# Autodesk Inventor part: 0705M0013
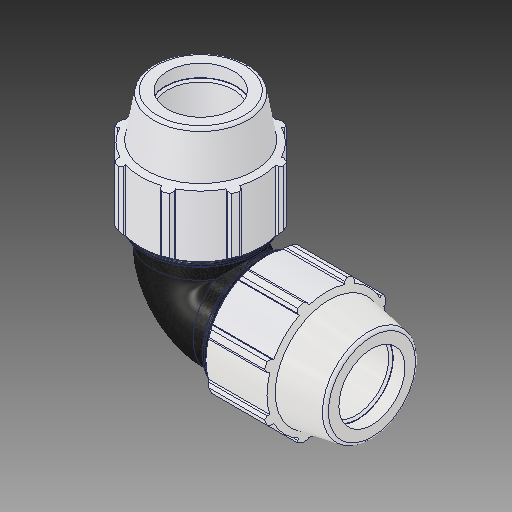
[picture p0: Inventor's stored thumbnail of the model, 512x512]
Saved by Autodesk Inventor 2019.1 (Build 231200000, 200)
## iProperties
Created: 2017-02
Part Number: 0705M0013
Material: PVC-Piping
Description: PLASSON 90° ELBOW 1 1/4'' - 1 1/4''
Document SubType Name: Modeling
Designer: KIM
Mass: 92.6774 g
Surface Area: 199.44 cm^2
Volume: 66.1981 cm^3
Density: 1.4 g/cm^3
Appearance: PTFE
Author: KIM
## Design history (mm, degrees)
derived "0705M0.ipt"
feature "Solid1::0705M0.ipt"
tag "TaggingFeature1"
body "Solid1"
other parameters: "d2" = 42.1, "d4" = 9.0805, "d5" = 27.2415, "d7" = 82.042, "d9" = 15.56657, "d11" = 2.72415, "d13" = 120 deg, "d14" = 58.94, "d15" = 10 deg, "d16" = 71.37654, "d18" = 2.105, "d19" = 35 deg, "d20" = 17.5 deg, "d21" = 76.29906, "d23" = 0, "d25" = 360 deg, "d27" = 1.64084, "d33" = 0.842, "d42" = 40.31742, "d43" = 2.46126, "d46" = 1.263, "d51" = 108.966, "d59" = 90 deg, "d63" = 83.058, "d64" = 37.89, "d67" = 61.5315, "d68" = 2.72415, "d70" = 90 deg, "d_" = 42.1, "E_" = 82.042, "A_" = 108.966, "l_" = 83.058
